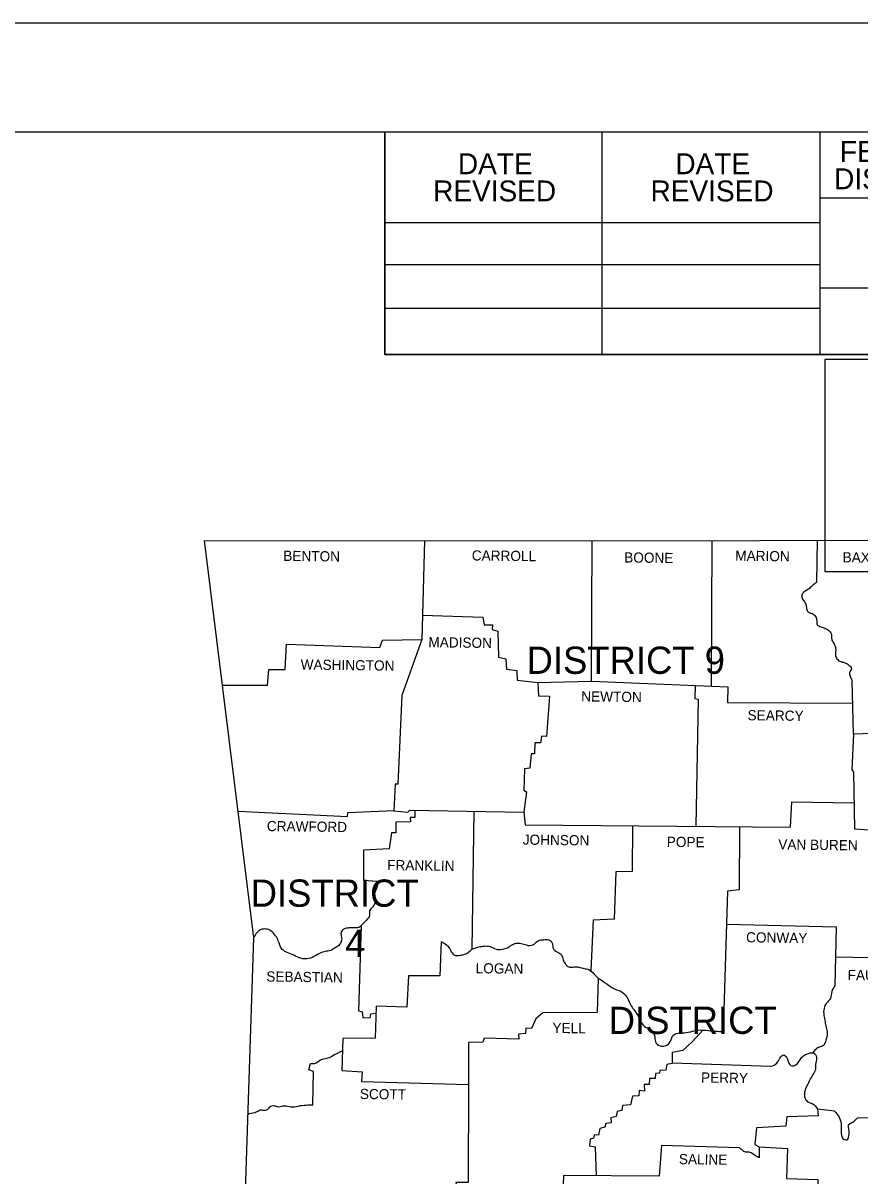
# Model space of a CAD drawing. Extents: x -0.3 to 2.65, y 0 to 1.9.
# Drawn here: x 1.0605 to 1.2203, y 0.6965 to 0.9167 of the extents above; entities that cross this region are included whole.
import ezdxf

# ---------------------------------------------------------------- set-up
doc = ezdxf.new("R2010")
doc.units = 0
for name, color, linetype in [('Default', 7, 'Continuous'), ('Level 9', 7, 'Continuous'), ('SHET_Border-Lines', 7, 'Continuous'), ('SHET_Border-Text', 7, 'Continuous')]:
    doc.layers.add(name, color=color, linetype=linetype)

msp = doc.modelspace()

# ---------------------------------------------------------------- linework, layer by layer
at = {"layer": 'Default'}
for p, q in [((1.2115, 0.7202), (1.21134, 0.72002)), ((1.10377, 0.70837), (1.10343, 0.70833))]:
    msp.add_line(p, q, dxfattribs=at)
for points in [[(1.09511, 0.81784), (1.16886, 0.81779), (1.23365, 0.81792), (1.31002, 0.81909), (1.34545, 0.81992)], [(1.09511, 0.81784), (1.10455, 0.74198), (1.10045, 0.61817)], [(1.1372, 0.81781), (1.13672, 0.79894)], [(1.13684, 0.80359), (1.14835, 0.80321), (1.14861, 0.80176), (1.15019, 0.80171), (1.15014, 0.80083), (1.1512, 0.80054), (1.1513, 0.79554), (1.15273, 0.79523), (1.15283, 0.79325), (1.15481, 0.793), (1.15491, 0.79115), (1.15886, 0.79073), (1.16912, 0.791), (1.1692, 0.81779)], [(1.19208, 0.81784), (1.19192, 0.79004)], [(1.21215, 0.81788), (1.21204, 0.80983)], [(1.23362, 0.81792), (1.23372, 0.80679), (1.23297, 0.80674), (1.23308, 0.79538), (1.22991, 0.79491), (1.23017, 0.79188), (1.23126, 0.79045), (1.23118, 0.78685), (1.22498, 0.78662), (1.22475, 0.78107), (1.2191, 0.78088), (1.21879, 0.77409), (1.21912, 0.77357), (1.21928, 0.76278), (1.229, 0.76213), (1.22887, 0.73809), (1.23665, 0.73789), (1.23665, 0.7134), (1.23053, 0.71294), (1.23009, 0.70759), (1.2198, 0.70752)], [(1.09854, 0.79022), (1.10724, 0.79019), (1.10745, 0.79318), (1.11059, 0.79318), (1.11087, 0.79805), (1.12869, 0.79743), (1.12921, 0.79878), (1.13672, 0.79894), (1.13289, 0.78825), (1.13214, 0.77131), (1.13159, 0.77129), (1.13134, 0.76618), (1.13401, 0.76595), (1.13442, 0.76636), (1.15618, 0.76595), (1.15641, 0.76353)], [(1.15886, 0.79073), (1.15896, 0.7882), (1.16106, 0.78809), (1.16051, 0.78042), (1.15955, 0.78044), (1.15937, 0.77922), (1.15828, 0.7792), (1.15823, 0.77712), (1.15755, 0.77707), (1.15732, 0.77437), (1.15631, 0.77424), (1.15618, 0.77015), (1.15665, 0.76981), (1.15618, 0.76595)], [(1.16912, 0.791), (1.19511, 0.78991), (1.19508, 0.78693), (1.21895, 0.78677)], [(1.2191, 0.78088), (1.21884, 0.79113)], [(1.18889, 0.79017), (1.18881, 0.78768), (1.18943, 0.78752), (1.18904, 0.76325)], [(1.10154, 0.76614), (1.12247, 0.76514), (1.12257, 0.76589), (1.13134, 0.76629)], [(1.13537, 0.76634), (1.13533, 0.76493), (1.13447, 0.76493), (1.1345, 0.7641), (1.13175, 0.76405), (1.1317, 0.76203), (1.13092, 0.76203), (1.13048, 0.75897), (1.12555, 0.75871), (1.12553, 0.75295), (1.12817, 0.75275)], [(1.15641, 0.76353), (1.20706, 0.76309), (1.20732, 0.76792), (1.21921, 0.76776)], [(1.14661, 0.76613), (1.14627, 0.73978)], [(1.1769, 0.76336), (1.17685, 0.75464), (1.17371, 0.75459), (1.17343, 0.74551), (1.16943, 0.74535), (1.16895, 0.73569)], [(1.19737, 0.76318), (1.19729, 0.75109), (1.19506, 0.75088), (1.19423, 0.72404)], [(1.12508, 0.74427), (1.12459, 0.728), (1.12532, 0.72782), (1.12542, 0.72673), (1.12682, 0.72666), (1.12693, 0.72741), (1.12792, 0.72757)], [(1.19486, 0.74455), (1.21583, 0.74403), (1.21557, 0.73278)], [(1.14041, 0.74123), (1.1401, 0.73472), (1.13416, 0.73467), (1.13382, 0.72873), (1.12796, 0.72889), (1.12778, 0.72279), (1.12161, 0.72271), (1.1214, 0.71659), (1.12532, 0.71639), (1.12516, 0.71449), (1.14558, 0.71393)], [(1.2157, 0.7383), (1.22887, 0.73809)], [(1.17039, 0.73425), (1.17018, 0.72769), (1.15981, 0.72764), (1.15844, 0.72647), (1.15763, 0.72466), (1.15652, 0.72471), (1.15647, 0.7237), (1.15514, 0.72354), (1.15519, 0.72261), (1.14858, 0.72277), (1.14832, 0.72204), (1.1456, 0.72194), (1.14558, 0.71393)], [(1.19037, 0.7243), (1.18831, 0.72209), (1.18655, 0.72041), (1.18447, 0.72007), (1.1845, 0.71792), (1.18349, 0.71779), (1.18331, 0.7167), (1.18214, 0.71659), (1.18209, 0.71613), (1.18128, 0.71607), (1.18126, 0.71511), (1.18014, 0.71506), (1.18007, 0.71397), (1.17913, 0.71397), (1.17918, 0.71268), (1.1782, 0.71278), (1.17812, 0.71177), (1.1769, 0.71169), (1.17656, 0.71003), (1.17501, 0.7099), (1.17485, 0.70897), (1.17402, 0.70876), (1.17382, 0.7078), (1.17278, 0.70759), (1.17286, 0.70661), (1.17182, 0.7065), (1.17164, 0.70578), (1.17068, 0.70552), (1.17044, 0.70427), (1.16969, 0.70435), (1.16948, 0.7037), (1.16881, 0.70347), (1.16873, 0.70223), (1.1698, 0.70204), (1.16999, 0.69651)], [(1.11588, 0.70998), (1.11603, 0.71641), (1.1151, 0.71672), (1.11541, 0.71794)], [(1.20335, 0.71737), (1.1845, 0.718)], [(1.14558, 0.71393), (1.14552, 0.69525), (1.14321, 0.6952), (1.14342, 0.69385), (1.14122, 0.69387), (1.14116, 0.69286), (1.13901, 0.69286), (1.13906, 0.69216), (1.1359, 0.69206), (1.13582, 0.68928), (1.13274, 0.68957), (1.13222, 0.66711)], [(1.21552, 0.70884), (1.21225, 0.70923), (1.21238, 0.70798), (1.20639, 0.70775), (1.20621, 0.70599), (1.20058, 0.70567), (1.20027, 0.70246), (1.2011, 0.70204), (1.2011, 0.69994)], [(1.19734, 0.70186), (1.18245, 0.7023), (1.18204, 0.69644), (1.16375, 0.69655), (1.16263, 0.66592)], [(1.2011, 0.70204), (1.20654, 0.70171), (1.20634, 0.696), (1.2123, 0.69577), (1.21243, 0.69079), (1.21523, 0.69056), (1.21523, 0.6897), (1.2179, 0.68949), (1.21798, 0.6863), (1.224, 0.6863), (1.22421, 0.68314), (1.22976, 0.68288), (1.22973, 0.67694)]]:
    msp.add_lwpolyline(points, dxfattribs=at)
for points in [[(1.21204, 0.80983), (1.21121, 0.80918), (1.21051, 0.80853), (1.2094, 0.80773), (1.20927, 0.807), (1.20963, 0.8063), (1.20999, 0.8057), (1.21015, 0.80487), (1.21046, 0.8042), (1.21121, 0.80389), (1.21189, 0.80332), (1.21209, 0.80251), (1.2122, 0.80174), (1.2129, 0.80137), (1.21373, 0.80106), (1.21453, 0.80052), (1.2149, 0.79987), (1.21495, 0.79896), (1.21528, 0.79831), (1.21565, 0.79746), (1.21573, 0.79678), (1.21565, 0.79611), (1.21585, 0.79546), (1.21643, 0.79481), (1.21746, 0.7945), (1.21821, 0.79406), (1.21873, 0.79341), (1.21837, 0.79266), (1.21845, 0.79196), (1.21884, 0.79113)], [(1.12817, 0.75275), (1.12817, 0.75179), (1.12781, 0.7508), (1.12757, 0.74992), (1.12773, 0.74878), (1.12732, 0.74787), (1.12672, 0.74712), (1.12672, 0.74624), (1.12604, 0.74528), (1.12529, 0.74452), (1.12467, 0.74395), (1.1235, 0.74388), (1.12254, 0.74382), (1.12161, 0.74349), (1.12125, 0.74279), (1.1214, 0.74175), (1.12104, 0.74074), (1.12011, 0.73999), (1.11904, 0.73947), (1.11795, 0.73929), (1.11642, 0.73856), (1.11507, 0.73799), (1.1136, 0.73804), (1.11225, 0.73864), (1.111, 0.73918), (1.11004, 0.73975), (1.10929, 0.74141), (1.10877, 0.74235), (1.10789, 0.74328), (1.10688, 0.74364), (1.106, 0.74354), (1.10455, 0.74198)], [(1.14041, 0.74123), (1.1414, 0.74061), (1.14218, 0.73957), (1.14285, 0.73869), (1.14402, 0.73864), (1.14492, 0.73882), (1.14627, 0.73978)], [(1.14627, 0.73978), (1.1478, 0.74027), (1.14889, 0.7404), (1.15001, 0.74019), (1.15115, 0.73973), (1.15234, 0.73986), (1.15325, 0.74017), (1.15418, 0.74076), (1.15517, 0.74095), (1.15615, 0.74076), (1.15717, 0.74048), (1.15823, 0.74082), (1.15888, 0.74139), (1.15997, 0.74159), (1.16095, 0.74159), (1.16163, 0.74082), (1.16176, 0.73996), (1.16264, 0.73921), (1.16339, 0.73869), (1.16365, 0.73776), (1.16404, 0.73706), (1.16445, 0.73659), (1.16505, 0.73633), (1.16606, 0.73641), (1.16762, 0.7361), (1.1686, 0.73589), (1.16954, 0.73508), (1.17039, 0.73425)], [(1.17039, 0.73425), (1.172, 0.73317), (1.1735, 0.73221), (1.17503, 0.73153), (1.17589, 0.73055), (1.17667, 0.72896), (1.17734, 0.728), (1.17812, 0.72681), (1.17874, 0.72551), (1.17968, 0.72476), (1.18069, 0.72414), (1.18118, 0.723), (1.18141, 0.72186), (1.18253, 0.72129), (1.18359, 0.72152), (1.18416, 0.72222), (1.18473, 0.72339), (1.18595, 0.72378), (1.18753, 0.72391), (1.18935, 0.72432), (1.1914, 0.72424), (1.19423, 0.72404)], [(1.21557, 0.73278), (1.21495, 0.73171), (1.21471, 0.73034), (1.21396, 0.72946), (1.21349, 0.7285), (1.21347, 0.72715), (1.21368, 0.72596), (1.21391, 0.72484), (1.21412, 0.72378), (1.21386, 0.72245), (1.21326, 0.72131), (1.21238, 0.72098), (1.2115, 0.7202)], [(1.11541, 0.71794), (1.1164, 0.71802), (1.11736, 0.71864), (1.11863, 0.71895), (1.11992, 0.7196), (1.12153, 0.72037)], [(1.20335, 0.71737), (1.20447, 0.71802), (1.20507, 0.71898), (1.20579, 0.71958), (1.20652, 0.71875), (1.20717, 0.71758), (1.20787, 0.71755), (1.20872, 0.71841), (1.20927, 0.71913), (1.20997, 0.71965), (1.21069, 0.71991), (1.21145, 0.71999), (1.21207, 0.71911), (1.21186, 0.71773), (1.21186, 0.71685), (1.21137, 0.71587), (1.2108, 0.71486), (1.21023, 0.71371), (1.20979, 0.71252), (1.20986, 0.7113), (1.21051, 0.71055), (1.21121, 0.71032), (1.21225, 0.70923)], [(1.11588, 0.70998), (1.11458, 0.70995), (1.11305, 0.70977), (1.11168, 0.70959), (1.11046, 0.70982), (1.10934, 0.70964), (1.10856, 0.70982), (1.10761, 0.70959), (1.10703, 0.70902), (1.10589, 0.70902), (1.10509, 0.70866), (1.10377, 0.70837)], [(1.21552, 0.70884), (1.2163, 0.70785), (1.21676, 0.70648), (1.21676, 0.70492), (1.2171, 0.70365), (1.21785, 0.70337), (1.21829, 0.70448), (1.21821, 0.70555), (1.21819, 0.70622), (1.21899, 0.70676), (1.2198, 0.70752)], [(1.2011, 0.69994), (1.19993, 0.70064), (1.19921, 0.70103), (1.1985, 0.70101), (1.19791, 0.70137), (1.19734, 0.70186)]]:
    msp.add_spline(points, degree=3, dxfattribs=at)
at = {"layer": 'Level 9'}
msp.add_lwpolyline([(1.21366, 0.81193), (1.39483, 0.81193), (1.39483, 0.85238), (1.21366, 0.85238)], close=True, dxfattribs=at)
at = {"layer": 'SHET_Border-Lines'}
for p, q in [((1.12962, 0.85338), (1.12962, 0.89583)), ((1.17114, 0.85338), (1.17114, 0.89583)), ((1.21266, 0.89583), (1.21266, 0.85338)), ((1.39583, 0.8832), (1.21266, 0.8832)), ((1.12962, 0.87856), (1.21266, 0.87856)), ((1.12962, 0.87057), (1.21266, 0.87057)), ((1.39583, 0.86601), (1.21266, 0.86601)), ((1.12962, 0.86223), (1.21266, 0.86223)), ((1.39583, 0.85338), (1.12962, 0.85338))]:
    msp.add_line(p, q, dxfattribs=at)
for points in [[(0, 0), (1.41667, 0), (1.41667, 0.91667), (0, 0.91667)], [(0.02083, 0.02083), (1.39583, 0.02083), (1.39583, 0.89583), (0.02083, 0.89583)], [(1.12962, 0.85338), (1.39583, 0.85338), (1.39583, 0.89583), (1.12962, 0.89583)]]:
    msp.add_lwpolyline(points, close=True, dxfattribs=at)

# ---------------------------------------------------------------- texts
at = {"layer": 'Default'}
for s, rotation, p in [('BENTON', 359.2874, (1.11022, 0.81395)), ('CARROLL', 359.267, (1.14622, 0.81403)), ('BOONE', 359.3139, (1.17532, 0.81364)), ('MARION', 359.2237, (1.19653, 0.81398)), ('BAXTER', 359.2892, (1.21703, 0.81367)), ('MADISON', 359.217, (1.13793, 0.79746)), ('WASHINGTON', 359.2079, (1.11354, 0.7932)), ('NEWTON', 359.303, (1.16712, 0.78711)), ('SEARCY', 359.2838, (1.19888, 0.78351)), ('CRAWFORD', 359.2748, (1.10709, 0.76234)), ('JOHNSON', 359.2575, (1.15595, 0.75975)), ('POPE', 359.3389, (1.18345, 0.75933)), ('VAN BUREN', 359.2547, (1.20474, 0.75884)), ('FRANKLIN', 359.1782, (1.13006, 0.7549)), ('CONWAY', 359.1737, (1.1986, 0.7411)), ('SEBASTIAN', 359.1959, (1.10699, 0.73361)), ('LOGAN', 359.3076, (1.14696, 0.73519)), ('FAULKNER', 359.2447, (1.21799, 0.73389)), ('YELL', 359.3097, (1.16162, 0.72378)), ('PERRY', 359.2992, (1.19, 0.71431)), ('SCOTT', 359.32, (1.12485, 0.71117)), ('SALINE', 359.1885, (1.18576, 0.69873))]:
    msp.add_text(s, height=0.001945, rotation=rotation, dxfattribs=at).set_placement(p)
for s, height, p in [('DISTRICT 9', 0.005203, (1.15669, 0.79237)), ('DISTRICT', 0.005203, (1.10401, 0.74789)), ('4', 0.0052, (1.12205, 0.73831)), ('DISTRICT', 0.005203, (1.17238, 0.7236))]:
    msp.add_text(s, height=height, dxfattribs=at).set_placement(p)
at = {"layer": 'SHET_Border-Text'}
for s, p in [('FED.RD.', (1.21651, 0.89012)), ('DATE', (1.14358, 0.8878)), ('DATE', (1.1851, 0.8878)), ('DIST.NO.', (1.21541, 0.88492)), ('REVISED', (1.13885, 0.8826)), ('REVISED', (1.18037, 0.8826))]:
    msp.add_text(s, height=0.004, dxfattribs=at).set_placement(p)

doc.saveas('drawing.dxf')
